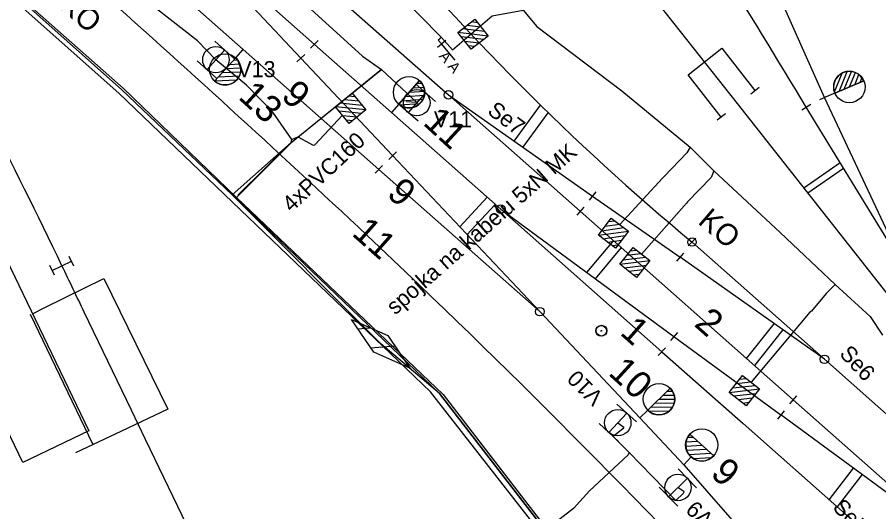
# Model space of a CAD drawing. Extents: x -496570 to -495506, y -1089156 to -1088046.
# Drawn here: x -495946.2 to -495866, y -1088709.5 to -1088663.4 of the extents above; entities that cross this region are included whole.
import ezdxf

# ---------------------------------------------------------------- set-up
doc = ezdxf.new("R2010")
doc.units = 0
for name, color, linetype in [('10', 7, 'Continuous'), ('11', 7, 'Continuous'), ('14', 7, 'Continuous'), ('15', 7, 'Continuous'), ('20', 7, 'Continuous'), ('27', 7, 'Continuous'), ('39', 7, 'Continuous'), ('54', 7, 'Continuous'), ('PŮVODNÍ_NÁVRH', 7, 'Continuous'), ('SEE', 7, 'Continuous')]:
    doc.layers.add(name, color=color, linetype=linetype)

msp = doc.modelspace()

# ---------------------------------------------------------------- linework, layer by layer
at = {"layer": '10'}
for p, q in [((-495877.889, -1088670.495), (-495877.103, -1088669.877)), ((-495880.247, -1088672.349), (-495881.033, -1088672.967))]:
    msp.add_line(p, q, dxfattribs=at)
msp.add_lwpolyline([(-495880.64, -1088672.658), (-495883.731, -1088668.728), (-495880.586, -1088666.255), (-495877.496, -1088670.186)], dxfattribs=at)
at = {"layer": '11'}
for p, q in [((-495872.933, -1088679.258), (-495869.554, -1088676.913)), ((-495872.561, -1088679.73), (-495869.241, -1088677.426)), ((-495891.876, -1088692.599), (-495891.776, -1088692.599)), ((-495891.837, -1088692.575), (-495891.737, -1088692.575))]:
    msp.add_line(p, q, dxfattribs=at)
for points in [[(-495899.915, -1088674.9), (-495897.476, -1088671.553)], [(-495899.107, -1088675.488), (-495896.753, -1088672.258)], [(-495904.997, -1088682.889), (-495902.427, -1088680.122)], [(-495904.319, -1088683.627), (-495901.695, -1088680.802)], [(-495893.146, -1088687.15), (-495890.686, -1088684.193)], [(-495892.343, -1088687.748), (-495889.918, -1088684.833)], [(-495878.283, -1088695.173), (-495875.71, -1088691.936)], [(-495877.518, -1088695.817), (-495874.897, -1088692.519)], [(-495870.578, -1088708.356), (-495868.314, -1088705.401)], [(-495869.816, -1088709.006), (-495867.52, -1088706.009)]]:
    msp.add_lwpolyline(points, dxfattribs=at)
for centre in [(-495891.826, -1088692.599), (-495891.787, -1088692.575)]:
    msp.add_circle(centre, 0.5, dxfattribs=at)
at = {"layer": '14'}
for p, q in [((-495925.163, -1088666.362), (-495912.526, -1088677.546)), ((-495918.533, -1088665.884), (-495911.355, -1088672.234)), ((-495919.797, -1088667.177), (-495911.25, -1088676.254)), ((-495892.641, -1088680.024), (-495884.47, -1088685.732)), ((-495893.767, -1088681.44), (-495873.948, -1088699.018)), ((-495885.041, -1088693.123), (-495875.095, -1088700.424)), ((-495888.216, -1088700.712), (-495884.123, -1088705.091))]:
    msp.add_line(p, q, dxfattribs=at)
for points in [[(-495842.928, -1088717.493), (-495843.661, -1088716.477), (-495851.703, -1088706.254), (-495860.009, -1088695.696), (-495879.111, -1088671.4), (-495889.727, -1088657.952), (-495895.948, -1088650.027), (-495908.172, -1088634.454), (-495920.247, -1088619.061), (-495937.589, -1088596.936)], [(-495863.612, -1088686.663), (-495871.01, -1088670.829), (-495876.153, -1088659.315), (-495885.306, -1088638.927), (-495892.793, -1088622.727)], [(-495851.703, -1088706.254), (-495858.66, -1088694.79), (-495863.612, -1088686.663), (-495872.713, -1088671.728)], [(-495920.141, -1088732.033), (-495934.255, -1088702.718), (-495935.575, -1088699.985), (-495939.964, -1088690.857)], [(-495886.163, -1088694.537), (-495878.59, -1088701.24), (-495849.995, -1088726.59), (-495837.458, -1088737.736), (-495818.246, -1088754.776)]]:
    msp.add_lwpolyline(points, dxfattribs=at)
msp.add_circle((-495883.36, -1088684.314), 0.4, dxfattribs=at)
for centre, major_axis, ratio, start_param, end_param in [((-495740.116, -1088511.814), (-173.671, 143.009), 0.996652, 1.373695, 1.566684), ((-496824.401, -1089653.614), (1059.037, -809), 0.998355, 1.469359, 1.495452), ((-496469.42, -1089273.532), (798.669, -137.95), 0.999908, 0.920538, 0.986213)]:
    msp.add_ellipse(centre, major_axis=major_axis, ratio=ratio, start_param=start_param, end_param=end_param, dxfattribs=at)
for points in [[(-495939.964, -1088690.857), (-495942.044, -1088686.532), (-495949.093, -1088672.316), (-495953.81, -1088663.645), (-495962.754, -1088650.285), (-495972.743, -1088638.936), (-495985.077, -1088627.584), (-495997.355, -1088618.062), (-496006.199, -1088611.844)], [(-495872.713, -1088671.728), (-495889.373, -1088645.185), (-495900.422, -1088629.274)]]:
    msp.add_spline(points, degree=3, dxfattribs=at)
at = {"layer": '15'}
for p, q in [((-495903.011, -1088664.282), (-495904.329, -1088664.119)), ((-495903.337, -1088663.864), (-495903.911, -1088663.793)), ((-495902.358, -1088665.118), (-495905.165, -1088664.772)), ((-495902.684, -1088664.7), (-495904.747, -1088664.446)), ((-495927.797, -1088665.579), (-495925.968, -1088667.23)), ((-495902.776, -1088665.444), (-495904.839, -1088665.189)), ((-495903.195, -1088665.771), (-495904.512, -1088665.608)), ((-495928.534, -1088668.233), (-495926.882, -1088666.405)), ((-495903.612, -1088666.097), (-495904.186, -1088666.026)), ((-495929.448, -1088667.408), (-495927.619, -1088669.059)), ((-495907.253, -1088671.207), (-495909.104, -1088669.58)), ((-495908.179, -1088670.393), (-495909.805, -1088672.245)), ((-495914.42, -1088671.177), (-495915.742, -1088671.044)), ((-495914.756, -1088670.767), (-495915.331, -1088670.709)), ((-495913.749, -1088671.998), (-495916.563, -1088671.716)), ((-495914.159, -1088672.334), (-495916.227, -1088672.126)), ((-495914.084, -1088671.588), (-495916.153, -1088671.38)), ((-495908.88, -1088673.058), (-495910.731, -1088671.431)), ((-495914.57, -1088672.67), (-495915.891, -1088672.537)), ((-495914.98, -1088673.005), (-495915.556, -1088672.948)), ((-495891.125, -1088682.414), (-495890.552, -1088682.334)), ((-495892.083, -1088683.685), (-495889.282, -1088683.292)), ((-495891.764, -1088683.261), (-495889.705, -1088682.973)), ((-495891.444, -1088682.837), (-495890.129, -1088682.653)), ((-495891.66, -1088684.004), (-495889.601, -1088683.715)), ((-495891.236, -1088684.323), (-495889.921, -1088684.139)), ((-495890.813, -1088684.643), (-495890.24, -1088684.562)), ((-495940.926, -1088686.549), (-495941.36, -1088685.648)), ((-495889.766, -1088685.963), (-495887.701, -1088685.722)), ((-495889.437, -1088685.546), (-495888.118, -1088685.392)), ((-495889.108, -1088685.131), (-495888.534, -1088685.063)), ((-495942.728, -1088687.416), (-495943.162, -1088686.515)), ((-495942.945, -1088686.966), (-495941.143, -1088686.098)), ((-495890.095, -1088686.379), (-495887.286, -1088686.05)), ((-495889.679, -1088686.707), (-495887.614, -1088686.466)), ((-495889.263, -1088687.037), (-495887.944, -1088686.882)), ((-495888.847, -1088687.365), (-495888.272, -1088687.298)), ((-495879.557, -1088697.92), (-495877.492, -1088697.682)), ((-495879.227, -1088697.504), (-495877.908, -1088697.352)), ((-495878.898, -1088697.089), (-495878.323, -1088697.023)), ((-495879.887, -1088698.335), (-495877.077, -1088698.012)), ((-495879.471, -1088698.665), (-495877.406, -1088698.427)), ((-495890.353, -1088699.419), (-495888.539, -1088701.087)), ((-495879.055, -1088698.995), (-495877.736, -1088698.843)), ((-495878.64, -1088699.324), (-495878.066, -1088699.258)), ((-495891.114, -1088702.067), (-495889.446, -1088700.253)), ((-495892.021, -1088701.233), (-495890.207, -1088702.901)), ((-495884.644, -1088705.458), (-495882.928, -1088707.226)), ((-495885.554, -1088708.058), (-495883.786, -1088706.342)), ((-495886.412, -1088707.174), (-495884.696, -1088708.942))]:
    msp.add_line(p, q, dxfattribs=at)
for points in [[(-495903.935, -1088666.348), (-495905.165, -1088664.772), (-495903.588, -1088663.541), (-495902.358, -1088665.118)], [(-495903.935, -1088666.348), (-495905.165, -1088664.772), (-495903.588, -1088663.541), (-495902.358, -1088665.118)], [(-495915.297, -1088673.264), (-495916.563, -1088671.716), (-495915.015, -1088670.45), (-495913.749, -1088671.998)], [(-495915.297, -1088673.264), (-495916.563, -1088671.716), (-495915.015, -1088670.45), (-495913.749, -1088671.998)], [(-495890.878, -1088682.088), (-495889.282, -1088683.292), (-495890.486, -1088684.889), (-495892.083, -1088683.685)], [(-495890.878, -1088682.088), (-495889.282, -1088683.292), (-495890.486, -1088684.889), (-495892.083, -1088683.685)], [(-495888.854, -1088684.81), (-495887.286, -1088686.05), (-495888.526, -1088687.619), (-495890.095, -1088686.379)], [(-495888.854, -1088684.81), (-495887.286, -1088686.05), (-495888.526, -1088687.619), (-495890.095, -1088686.379)], [(-495878.643, -1088696.768), (-495877.077, -1088698.012), (-495878.32, -1088699.578), (-495879.887, -1088698.335)], [(-495878.643, -1088696.768), (-495877.077, -1088698.012), (-495878.32, -1088699.578), (-495879.887, -1088698.335)]]:
    msp.add_lwpolyline(points, close=True, dxfattribs=at)
for points in [[(-495903.935, -1088666.348), (-495905.165, -1088664.772), (-495903.588, -1088663.541), (-495902.358, -1088665.118), (-495903.935, -1088666.348)], [(-495903.935, -1088666.348), (-495905.165, -1088664.772), (-495903.588, -1088663.541), (-495902.358, -1088665.118), (-495903.935, -1088666.348)], [(-495915.297, -1088673.264), (-495916.563, -1088671.716), (-495915.015, -1088670.45), (-495913.749, -1088671.998), (-495915.297, -1088673.264)], [(-495915.297, -1088673.264), (-495916.563, -1088671.716), (-495915.015, -1088670.45), (-495913.749, -1088671.998), (-495915.297, -1088673.264)], [(-495890.878, -1088682.088), (-495889.282, -1088683.292), (-495890.486, -1088684.889), (-495892.083, -1088683.685), (-495890.878, -1088682.088)], [(-495890.878, -1088682.088), (-495889.282, -1088683.292), (-495890.486, -1088684.889), (-495892.083, -1088683.685), (-495890.878, -1088682.088)], [(-495888.854, -1088684.81), (-495887.286, -1088686.05), (-495888.526, -1088687.619), (-495890.095, -1088686.379), (-495888.854, -1088684.81)], [(-495888.854, -1088684.81), (-495887.286, -1088686.05), (-495888.526, -1088687.619), (-495890.095, -1088686.379), (-495888.854, -1088684.81)], [(-495878.643, -1088696.768), (-495877.077, -1088698.012), (-495878.32, -1088699.578), (-495879.887, -1088698.335), (-495878.643, -1088696.768)], [(-495878.643, -1088696.768), (-495877.077, -1088698.012), (-495878.32, -1088699.578), (-495879.887, -1088698.335), (-495878.643, -1088696.768)]]:
    msp.add_lwpolyline(points, dxfattribs=at)
for centre in [(-495927.706, -1088667.315), (-495908.994, -1088671.324), (-495890.278, -1088701.156), (-495884.667, -1088707.196)]:
    msp.add_circle(centre, 1.232, dxfattribs=at)
at = {"layer": '20'}
for p, q in [((-495906.296, -1088665.529), (-495907.064, -1088666.169)), ((-495905.412, -1088667.369), (-495906.68, -1088665.849))]:
    msp.add_line(p, q, dxfattribs=at)
at = {"layer": '27'}
for p, q in [((-495918.175, -1088665.535), (-495918.891, -1088666.233)), ((-495925.851, -1088667.126), (-495925.163, -1088666.362)), ((-495927.825, -1088669.301), (-495925.859, -1088667.132)), ((-495927.817, -1088669.295), (-495925.852, -1088667.126)), ((-495919.436, -1088666.831), (-495920.158, -1088667.523)), ((-495925.387, -1088668.097), (-495926.796, -1088668.167)), ((-495925.466, -1088667.73), (-495926.445, -1088667.779)), ((-495925.653, -1088667.369), (-495926.093, -1088667.391)), ((-495925.52, -1088668.844), (-495927.5, -1088668.942)), ((-495925.402, -1088668.468), (-495927.148, -1088668.554)), ((-495870.097, -1088670.325), (-495869.381, -1088668.567)), ((-495869.669, -1088670.267), (-495868.915, -1088668.417)), ((-495869.18, -1088670.062), (-495868.511, -1088668.416)), ((-495868.691, -1088669.854), (-495868.147, -1088668.517)), ((-495868.203, -1088669.649), (-495867.82, -1088668.708)), ((-495927.824, -1088669.301), (-495927.825, -1088669.301)), ((-495925.788, -1088669.228), (-495927.793, -1088669.327)), ((-495926.48, -1088669.632), (-495927.071, -1088669.661)), ((-495910.681, -1088671.456), (-495908.757, -1088669.25)), ((-495908.757, -1088669.25), (-495910.68, -1088671.457)), ((-495909.007, -1088669.537), (-495908.532, -1088669.504)), ((-495867.364, -1088669.295), (-495870.062, -1088670.432)), ((-495870.061, -1088670.432), (-495867.364, -1088669.295)), ((-495867.714, -1088669.443), (-495867.534, -1088669.001)), ((-495909.704, -1088670.337), (-495908.264, -1088670.238)), ((-495909.356, -1088669.937), (-495908.343, -1088669.868)), ((-495870.062, -1088670.433), (-495871.01, -1088670.829)), ((-495870.062, -1088670.432), (-495870.061, -1088670.432)), ((-495910.402, -1088671.136), (-495908.408, -1088670.999)), ((-495910.054, -1088670.736), (-495908.282, -1088670.615)), ((-495906.039, -1088670.587), (-495892.641, -1088680.024)), ((-495871.463, -1088671.04), (-495870.557, -1088670.618)), ((-495910.682, -1088671.457), (-495911.355, -1088672.234)), ((-495910.68, -1088671.457), (-495910.681, -1088671.456)), ((-495910.591, -1088671.525), (-495908.697, -1088671.395)), ((-495873.14, -1088671.988), (-495872.286, -1088671.468)), ((-495910.9, -1088675.897), (-495911.6, -1088676.611)), ((-495912.179, -1088677.186), (-495912.873, -1088677.906)), ((-495897.546, -1088690.805), (-495912.526, -1088677.546)), ((-495892.329, -1088679.633), (-495892.953, -1088680.415)), ((-495901.166, -1088681.255), (-495885.041, -1088693.123)), ((-495893.437, -1088681.064), (-495894.097, -1088681.816)), ((-495883.008, -1088683.959), (-495883.712, -1088684.669)), ((-495884.14, -1088685.356), (-495884.8, -1088686.108)), ((-495871.032, -1088695.249), (-495884.47, -1088685.732)), ((-495884.713, -1088692.746), (-495885.369, -1088693.5)), ((-495885.818, -1088694.175), (-495886.508, -1088694.899)), ((-495887.484, -1088699.989), (-495885.396, -1088697.938)), ((-495885.396, -1088697.938), (-495887.483, -1088699.989)), ((-495886.046, -1088698.576), (-495885.03, -1088698.585)), ((-495885.667, -1088698.204), (-495885.19, -1088698.208)), ((-495886.803, -1088699.319), (-495885.027, -1088699.335)), ((-495886.424, -1088698.948), (-495884.98, -1088698.96)), ((-495873.616, -1088698.644), (-495874.28, -1088699.392)), ((-495887.485, -1088699.989), (-495888.216, -1088700.712)), ((-495887.483, -1088699.989), (-495887.484, -1088699.989)), ((-495887.399, -1088700.064), (-495885.501, -1088700.081)), ((-495887.181, -1088699.691), (-495885.183, -1088699.708)), ((-495874.781, -1088700.035), (-495875.409, -1088700.813)), ((-495858.985, -1088712.277), (-495875.095, -1088700.424)), ((-495883.769, -1088702.518), (-495883.275, -1088702.492)), ((-495881.337, -1088704.233), (-495883.569, -1088702.229)), ((-495883.569, -1088702.229), (-495881.337, -1088704.233)), ((-495883.946, -1088703.33), (-495882.434, -1088703.248)), ((-495883.918, -1088702.927), (-495882.855, -1088702.87)), ((-495883.865, -1088703.726), (-495882.012, -1088703.626)), ((-495883.66, -1088704.116), (-495881.592, -1088704.004)), ((-495883.455, -1088704.347), (-495884.123, -1088705.091)), ((-495883.258, -1088704.494), (-495881.52, -1088704.4))]:
    msp.add_line(p, q, dxfattribs=at)
for points in [[(-495919.797, -1088667.177), (-495946.901, -1088638.3)], [(-495948.204, -1088639.594), (-495918.533, -1088665.884)], [(-495925.163, -1088666.362), (-495937.6, -1088655.358), (-495950.037, -1088644.354)], [(-495871.01, -1088670.829), (-495876.153, -1088659.315), (-495881.299, -1088647.795)], [(-495918.486, -1088659.58), (-495906.039, -1088670.587), (-495893.767, -1088681.44)], [(-495863.612, -1088686.663), (-495871.01, -1088670.829)], [(-495858.66, -1088694.79), (-495863.612, -1088686.663), (-495872.713, -1088671.728)], [(-495911.355, -1088672.234), (-495901.166, -1088681.255), (-495886.163, -1088694.537)], [(-495888.216, -1088700.712), (-495897.546, -1088690.805), (-495911.25, -1088676.254)], [(-495858.601, -1088706.274), (-495871.032, -1088695.249), (-495883.36, -1088684.314)], [(-495873.948, -1088699.018), (-495858.985, -1088712.277), (-495848.789, -1088721.31)], [(-495884.123, -1088705.091), (-495873.19, -1088717.6), (-495862.268, -1088730.126)]]:
    msp.add_lwpolyline(points, dxfattribs=at)
for centre, radius in [((-495926.841, -1088668.216), 1.462), ((-495909.713, -1088670.348), 1.462), ((-495868.705, -1088669.859), 1.462), ((-495906.039, -1088670.587), 0.4), ((-495901.166, -1088681.255), 0.4), ((-495897.546, -1088690.805), 0.4), ((-495871.032, -1088695.249), 0.4), ((-495886.433, -1088698.959), 1.462), ((-495882.453, -1088703.231), 1.5)]:
    msp.add_circle(centre, radius, dxfattribs=at)
for centre, radius, start, end in [((-495926.842, -1088668.216), 1.464, 227.84824, 47.80909), ((-495868.712, -1088669.864), 1.464, 22.86387, 202.82472), ((-495909.719, -1088670.353), 1.464, 228.94652, 48.90737), ((-495886.44, -1088698.963), 1.464, 224.52012, 44.48097), ((-495882.453, -1088703.231), 1.5, 138.08481, 318.08481)]:
    msp.add_arc(centre, radius, start, end, dxfattribs=at)
at = {"layer": '39'}
for points in [[(-495957.648, -1088680.075), (-495951.471, -1088677.138), (-495939.541, -1088701.909), (-495945.69, -1088704.866), (-495951.872, -1088692.057), (-495957.648, -1088680.075)], [(-495944.797, -1088690.995), (-495943.626, -1088690.416), (-495938.152, -1088687.711), (-495932.195, -1088699.91), (-495936.484, -1088701.941), (-495940.773, -1088703.972)], [(-495939.137, -1088703.208), (-495944.983, -1088691.07)]]:
    msp.add_lwpolyline(points, dxfattribs=at)
at = {"layer": '54'}
for points in [[(-495953.449, -1088622.609), (-495941.984, -1088632.338), (-495925.232, -1088646.389), (-495920.238, -1088651.101), (-495918.659, -1088652.712), (-495917.444, -1088654.066), (-495914.993, -1088656.798), (-495906.695, -1088665.242), (-495905.674, -1088666.382), (-495901.99, -1088663.238), (-495899.101, -1088662.686), (-495897.827, -1088664.209), (-495889.9, -1088670.206), (-495883.539, -1088675.466), (-495881.314, -1088677.661), (-495875.162, -1088683.433), (-495870.028, -1088688.282), (-495866.758, -1088691.249), (-495865.624, -1088692.99)], [(-495969.086, -1088638.597), (-495966.23, -1088641.05), (-495951.776, -1088656.491), (-495936.467, -1088670.11), (-495926.204, -1088679.924), (-495906.892, -1088698.439), (-495894.264, -1088714.786), (-495868.546, -1088742.283), (-495860.148, -1088746.773), (-495854.533, -1088753.524)], [(-495940.107, -1088642.839), (-495939.73, -1088643.48), (-495939.623, -1088643.533), (-495934.288, -1088648.42), (-495926.53, -1088655.663), (-495924.959, -1088656.85), (-495921.609, -1088659.97), (-495921.6, -1088660.089), (-495914.058, -1088666.995), (-495912.283, -1088668.239), (-495920.741, -1088675.088), (-495925.773, -1088680.163)], [(-495920.648, -1088674.745), (-495922.401, -1088672.205), (-495924.867, -1088669.691), (-495927.708, -1088667.319), (-495929.41, -1088665.543), (-495939.603, -1088657.579), (-495941.948, -1088655.34), (-495937.942, -1088651.415), (-495936.4, -1088653.57), (-495934.45, -1088655.41), (-495933.97, -1088654.96), (-495933.83, -1088654.82), (-495934.52, -1088654.32)], [(-495791.286, -1088790.273), (-495804.369, -1088777.872), (-495811.106, -1088771.12), (-495824.244, -1088760.551), (-495840.179, -1088747.357), (-495841.548, -1088746.404), (-495845, -1088746.917), (-495854.533, -1088753.524), (-495860.828, -1088746.983), (-495869.129, -1088742.363), (-495894.734, -1088714.89), (-495907.733, -1088698.276), (-495926.154, -1088680.584), (-495936.743, -1088670.436), (-495952.112, -1088656.757)], [(-495951.647, -1088656.374), (-495945.893, -1088661.488), (-495936.346, -1088669.973), (-495925.773, -1088680.163), (-495906.553, -1088698.536), (-495896.884, -1088711.088), (-495893.995, -1088714.839), (-495868.155, -1088742.416), (-495860.018, -1088746.657), (-495854.533, -1088753.524), (-495845, -1088746.917), (-495841.548, -1088746.404), (-495840.19, -1088746.67), (-495839.894, -1088747.064), (-495839.734, -1088747.366), (-495839.482, -1088747.646), (-495839.66, -1088747.957), (-495839.679, -1088748.032), (-495838.294, -1088748.402), (-495823.909, -1088760.307), (-495810.91, -1088770.79), (-495804.093, -1088777.585), (-495801.02, -1088780.504), (-495790.99, -1088790.03)], [(-495906.695, -1088665.242), (-495907.001, -1088665.491), (-495906.68, -1088665.849)], [(-495912.283, -1088668.239), (-495908.992, -1088671.319), (-495909.94, -1088671.24)], [(-495926.204, -1088679.924), (-495920.709, -1088675.022), (-495920.648, -1088674.745), (-495920.08, -1088674.5), (-495918.65, -1088675.27), (-495918.49, -1088675.26), (-495915.93, -1088672.49)], [(-495883.539, -1088675.466), (-495883.83, -1088676), (-495885.95, -1088678.21), (-495886.1, -1088678.37), (-495890.08, -1088682.69)], [(-495881.314, -1088677.661), (-495881.57, -1088678.29), (-495883.78, -1088680.57), (-495883.87, -1088680.68), (-495888.07, -1088685.43)], [(-495870.028, -1088688.282), (-495870.88, -1088689.12), (-495872.24, -1088690.76), (-495872.38, -1088690.84), (-495877.86, -1088697.39)], [(-495890.28, -1088701.16), (-495889.7, -1088701.57), (-495889.79, -1088701.73), (-495890.71, -1088702.45), (-495889.22, -1088703.95), (-495889.32, -1088704.14), (-495892.9, -1088707.51), (-495894.39, -1088709.17), (-495896.884, -1088711.088)], [(-495889.22, -1088703.95), (-495884.88, -1088708.42), (-495884.15, -1088707.74), (-495884.1, -1088707.59), (-495884.67, -1088707.2)]]:
    msp.add_lwpolyline(points, dxfattribs=at)
at = {"layer": 'PŮVODNÍ_NÁVRH'}
msp.add_line((-495892.9, -1088707.51), (-495889.32, -1088704.14), dxfattribs=at)
for points in [[(-495905.674, -1088666.382), (-495901.99, -1088663.238), (-495899.101, -1088662.686), (-495897.827, -1088664.209)], [(-495925.67, -1088679.955), (-495920.709, -1088675.022), (-495912.283, -1088668.239)]]:
    msp.add_lwpolyline(points, dxfattribs=at)
at = {"layer": 'SEE'}
for p, q in [((-495914.496, -1088692.401), (-495913.371, -1088692.3)), ((-495913.278, -1088694.175), (-495911.05, -1088694)), ((-495910.242, -1088695.81), (-495909.83, -1088695.773))]:
    msp.add_line(p, q, dxfattribs=at)
msp.add_lwpolyline([(-495845, -1088746.917), (-495854.533, -1088753.524), (-495860.148, -1088746.773), (-495868.546, -1088742.283), (-495894.264, -1088714.786), (-495906.892, -1088698.439), (-495912.357, -1088693.808), (-495926.204, -1088679.924), (-495936.467, -1088670.11), (-495951.776, -1088656.491), (-495966.23, -1088641.05), (-495966.883, -1088640.489), (-495967.344, -1088640.093), (-495969.086, -1088638.597), (-495972.985, -1088642.454), (-495974.115, -1088643.402), (-495975.48, -1088645.263)], dxfattribs=at)
msp.add_lwpolyline([(-495915.063, -1088691.55), (-495911.705, -1088693.026), (-495909.651, -1088696.066), (-495913.009, -1088694.59)], close=True, dxfattribs=at)

# ---------------------------------------------------------------- texts
at = {"layer": '14'}
for s, height, rotation, p in [('KO', 2, 319.41817, (-495942.396, -1088662.423)), ('9', 2.5, 318.48058, (-495921.737, -1088670.85)), ('9', 2.5, 318.48058, (-495911.893, -1088679.96)), ('KO', 2, 319.41817, (-495882.901, -1088682.523)), ('11', 2.5, 318.48058, (-495915.137, -1088683.625)), ('2', 2.5, 318.48058, (-495883.254, -1088692.069)), ('1', 2.5, 318.478, (-495890.166, -1088692.867))]:
    msp.add_text(s, height=height, rotation=rotation, dxfattribs=at).set_placement(p)
at = {"layer": '15'}
for s, p in [('V13', (-495925.721, -1088668.945)), ('V11', (-495907.409, -1088673.622))]:
    msp.add_text(s, height=1.5, dxfattribs=at).set_placement(p)
for s, rotation, p in [('V10', 135.20536, (-495891.522, -1088698.644)), ('V9', 137.83154, (-495881.223, -1088709.96))]:
    msp.add_text(s, height=1.5, rotation=rotation, dxfattribs=at).set_placement(p)
at = {"layer": '20'}
for s, height, rotation, p in [('  A A', 1, 309.83619, (-495907.455, -1088666.44)), ('Se7', 1.5, 323.04383, (-495902.513, -1088672.288)), ('Se6', 1.5, 313.10181, (-495869.71, -1088694.802)), ('Se5', 1.5, 313.62523, (-495870.344, -1088709.134))]:
    msp.add_text(s, height=height, rotation=rotation, dxfattribs=at).set_placement(p)
at = {"layer": '27'}
for s, p in [('13', (-495925.716, -1088670.886)), ('11', (-495908.512, -1088673.305)), ('10', (-495891.249, -1088696.619)), ('9', (-495881.74, -1088706.032))]:
    msp.add_text(s, height=2.5, rotation=317.44522, dxfattribs=at).set_placement(p)
at = {"layer": '54'}
msp.add_text('4xPVC160', height=1.5, rotation=43.26601, dxfattribs=at).set_placement((-495920.663, -1088681.603))
at = {"layer": 'SEE'}
msp.add_text('spojka na kabelu 5xN MK', height=1.5, rotation=41.44671, dxfattribs=at).set_placement((-495911.006, -1088691.171))

doc.saveas('drawing.dxf')
